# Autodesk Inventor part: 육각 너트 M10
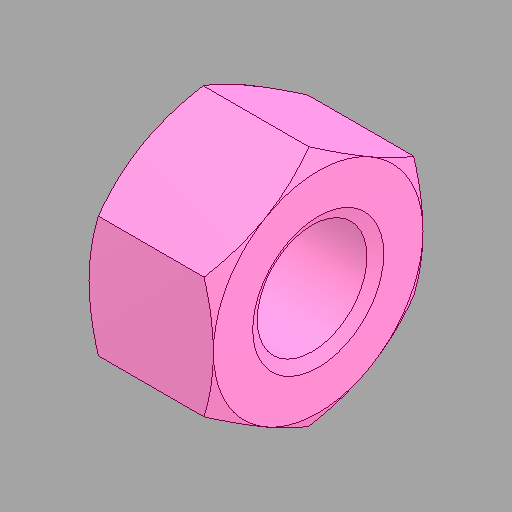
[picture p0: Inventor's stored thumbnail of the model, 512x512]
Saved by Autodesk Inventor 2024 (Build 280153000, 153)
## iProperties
Created: 2025-02
Part Number: 육각 너트 M10
Material: 강철, 연강
Description: 6각 너트 및 6각 가는 너트
Document SubType Name: Modeling
Designer: kh_501
Density: 7.85 g/cm^3
Appearance: 기본값
Author: jhkim
Sending System: Autodesk Inventor 2025
Preprocessor: ST-DEVELOPER v20
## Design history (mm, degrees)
feature "Solid1"
node "솔리드1"
